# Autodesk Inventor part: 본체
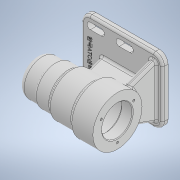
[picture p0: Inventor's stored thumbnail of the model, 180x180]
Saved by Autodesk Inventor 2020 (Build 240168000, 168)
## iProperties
Created: 2021-10
Part Number: 본체
Material: 일반
Document SubType Name: Modeling
Designer: user
Density: 1 g/cm^3
Appearance: 기본값
Author: user
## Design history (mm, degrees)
sketch "스케치1"
  geometry: L1 (-56, -45)-(56, -45); L2 (56, -45)-(56, 45); L3 (56, 45)-(-56, 45); L4 (-56, 45)-(-56, -45); L5 (-56, -45)-(56, 45); L6 (56, -45)-(-56, 45); 1 further point
  constraints: 12 end point, 2 midpoint, 2 parallel, 1 horizontal, 1 perpendicular
  dimensions: "d0" = 112 distance of L2.end L3.end; "d1" = 90 distance of L3.end L1.start
extrude "돌출1" new body sketch "스케치1" distance "d2" = 8; taper "d3" = 0 deg
sketch "스케치2"
  geometry: L1 (62.238, 70)-(-57.921, 70); L2 (10, 100)-(10, 97); L3 (10, 97)-(32, 97); L4 (32, 97)-(32, 95); L5 (56, 95)-(56, 70); L6 (50, 70)-(50, 77.5); L7 (47, 80.5)-(47, 80.5); L8 (47, 80.5)-(47, 85.7); L9 (46.7, 86)-(43, 86); L10 (43, 86)-(43, 87.2); L11 (25, 87.5)-(25, 90.7); L12 (24.7, 91)-(13, 91); L13 (13, 91)-(13, 91); L14 (10, 94)-(-38, 94); L15 (-41, 91)-(-41, 91); L16 (-41, 91)-(-56, 91); L17 (-56, 0)-(-56, 8) reference; L18 (10, 100)-(-24, 100); L19 (-24, 100)-(-24, 104); L20 (-24, 104)-(-56, 104); L21 (-56, 104)-(-56, 91); L22 (42.7, 87.5)-(25, 87.5); L23 (56, 95)-(32, 95); A1 r 0.3 centre (46.7, 85.7) between (47, 85.7) and (46.7, 86); A2 r 0.3 centre (42.7, 87.2) between (43, 87.2) and (42.7, 87.5); A3 r 0.3 centre (24.7, 90.7) between (25, 90.7) and (24.7, 91); A4 r 3 centre (47, 77.5) between (50, 77.5) and (47, 80.5); A5 r 3 centre (10, 91) between (13, 91) and (10, 94); A6 r 3 centre (-38, 91) between (-38, 94) and (-41, 91); 5 further points
  constraints: 44 end point, 13 perpendicular, 12 point on circle, 12 tangent, 6 centre point, 4 equal radius, 4 point on line, 3 horizontal, 1 vertical
  dimensions: "d4" = 70 distance from line of point (0, 0) L1; "d5" = 120.15879 distance of L1.start L1.end; "d8" = 24 distance between parallel lines of L4 L5; "d9" = 46 distance between parallel lines of L2 L5; "d10" = 112 distance between parallel lines of L21 L5; "d11" = 80 distance between parallel lines of L19 L5; "d12" = 15 distance between parallel lines of L15 L21; "d14" = 6 distance between parallel lines of L6 L5; "d15" = 3 distance between parallel lines of L8 L6; "d16" = 4 distance from line of L9.end L8; "d17" = 18 distance from line of L11 L9.end; "d18" = 12 distance from line of point (13, 94) L11; "d19" = 42 diameter of L16 L1; "d20" = 48 diameter of L14 L1; "d21" = 21 diameter of L7 L1; "d22" = 32 diameter of L9 L1; "d23" = 35 diameter of L22 L1; "d24" = 42 diameter of L12 L1; "d25" = 50 diameter of L23 L1; "d26" = 54 diameter of L3 L1; "d27" = 60 diameter of L18 L1; "d28" = 68 diameter of L20 L1; "d29" = 56 distance from line of point (0, 0) L5; "d30" = 0.3 radius of A1; "d31" = 3 radius of A4
revolve "회전1" sketch "스케치2" stored, may be unused: angle "d32" = 90 deg
sketch "스케치4"
  geometry: L1 (-29, 4)-(48, 4); L2 (48, 4)-(48, -4); L3 (48, -4)-(-29, -4); L4 (-29, -4)-(-29, 4); L5 (-29, 4)-(48, -4); L6 (48, 4)-(-29, -4); L7 (56, -45)-(56, 45) reference; 2 further points
  constraints: 12 end point, 2 midpoint, 2 parallel, 1 horizontal, 1 perpendicular
  dimensions: "d34" = 8 distance between parallel lines of L7 L2; "d35" = 77 distance of L2.end L3.end; "d36" = 8 distance of L1.end L2.end; "d37" = 0 vertical distance of point (0, 0) point (9.5, 0)
extrude "돌출2" join sketch "스케치4" stored distance "d38" = 8; taper "d39" = 0 deg
sketch "스케치5"
  geometry: L1 (0, 49)-(0, -41) reference; L2 (0, -33)-(-37.342, -19.409); L3 (0, 41)-(-37.342, 27.409); A1 r 34 centre (-62, 4) between (-28.236, 8) and (-28.236, 0) reference; 1 further point
  constraints: 4 end point, 2 point on circle, 2 point on line
  dimensions: "d40" = 8 distance of L1.end L2.start; "d41" = 8 distance of L1.start L3.start; "d42" = 110 deg angle of L1 L2; "d43" = 110 deg angle of L1 L3
feature "리브1" sketch "스케치5" dims "d44" = 1, "d45" = 8, "d46" = 0, "d47" = 0, "d48" = 1, "d49" = 1
sketch "스케치6"
  geometry: L1 (28.236, 41)-(28.236, -49) reference; L2 (28.236, 33)-(-9.106, 19.409); A1 r 34 centre (-33.764, -4) between (0, 0) and (0, -8) reference; 1 further point
  constraints: 2 end point, 1 point on circle, 1 point on line
  dimensions: "d50" = 8 distance of L1.start L2.start; "d51" = 110 deg angle of L1 L2
feature "리브2" sketch "스케치6" dims "d52" = 1, "d53" = 8, "d54" = 0, "d55" = 0, "d56" = 1, "d57" = 1
feature "면 기울기1" dims angle "d59" = 15 deg
sketch "스케치8"
  geometry: L1 (-48, 33)-(-24, 33); L2 (-43.5, 28.5)-(-28.5, 28.5); L3 (-28.5, 37.5)-(-43.5, 37.5); L4 (-56, 45)-(-56, -45) reference; L5 (-8, 33)-(16, 33); L6 (-3.5, 28.5)-(11.5, 28.5); L7 (11.5, 37.5)-(-3.5, 37.5); A1 r 4.5 centre (-43.5, 33) between (-43.5, 37.5) and (-43.5, 28.5); A2 r 4.5 centre (-28.5, 33) between (-28.5, 28.5) and (-28.5, 37.5); A3 r 4.5 centre (-3.5, 33) between (-3.5, 37.5) and (-3.5, 28.5); A4 r 4.5 centre (11.5, 33) between (11.5, 28.5) and (11.5, 37.5); 3 further points
  constraints: 16 end point, 12 point on circle, 8 tangent, 4 centre point, 4 point on line, 2 horizontal, 2 midpoint, 2 parallel
  dimensions: "d60" = 9 diameter of A2; "d61" = 15 distance of A2.centre A1.centre; "d62" = 20 distance from line of L4 point (-36, 33); "d63" = 33 vertical distance of point (0, 0) point (-36, 33); "d64" = 9 diameter of A4; "d65" = 15 distance of A4.centre A3.centre; "d66" = 25 distance of A2.centre A3.centre; "d67" = 33 vertical distance of point (0, 0) point (4, 33)
extrude "돌출3" cut sketch "스케치8" distance "d68" = 20; taper "d69" = 0 deg
sketch "스케치9"
  geometry: L1 (-56, 45)-(-56, -45) reference; A1 r 4.5 centre (-43.5, 33) between (-43.5, 37.5) and (-43.5, 28.5) reference; 2 further points
  constraints: 1 other
  dimensions: "d70" = 12 distance from line of L1 point (-44, 0); "d71" = 33 vertical distance of point (-44, 0) A1.centre
feature "엠보싱1" sketch "스케치9" dims "d0" = 112, "d1" = 90, "d4" = 70, "d5" = 120.15879, "d8" = 24, "d9" = 46, "d10" = 112, "d11" = 80, "d12" = 15, "d14" = 6, "d15" = 3, "d16" = 4, "d17" = 18, "d18" = 12, "d19" = 42, "d20" = 48, "d21" = 21, "d22" = 32, "d23" = 35, "d24" = 42, "d25" = 50, "d26" = 54, "d27" = 60, "d28" = 68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
sketch "스케치10"
  geometry: L1 (0, 0)-(-22.517, 13); L2 (0, 0)-(0, -26); C1 r 34 at (0, 0) reference; C2 r 7.5 at (0, 0) reference; A1 r 26 centre (0, 0) between (0, -26) and (-22.517, 13); 2 further points
  constraints: 4 end point, 2 coincident, 2 point on circle, 1 centre point, 1 vertical
  dimensions: "d74" = 52 diameter of A1; "d75" = 120 deg angle of L2 L1
hole "구멍1" sketch "스케치10" at (-22.517, 13) diameter "d76" = 3.242; stored, may be unused: countersink angle "d80" = 90 deg, drill point angle "d82" = 118 deg; dims "d77" = 8, "d78" = 4, "d79" = 2, "d81" = 11
fillet "모깎기1" dims "d86" = 8
fillet "모깎기2" dims "d87" = 12
fillet "모깎기3" dims "d88" = 3
fillet "모깎기4" dims "d89" = 3
fillet "모깎기5" dims "d90" = 3
fillet "모깎기6" dims "d91" = 3
chamfer "모따기1" distance "d92" = 1; stored, may be unused: second distance "d93" = 2, angle "d94" = 45 deg
fillet "모깎기7" dims "d95" = 3
fillet "모깎기8" dims "d96" = 3
fillet "모깎기9" dims "d97" = 3
node "솔리드1"
mirror "미러1"
pattern_circular "원형 패턴1" dims angle "d84" = 360 deg
feature "A9D066F2-1C7D-4E18-AEED-F7BC21143FA4" dims "d76" = 3.242, "d77" = 8, "d78" = 4, "d79" = 2, "d80" = 90 deg, "d81" = 11, "d82" = 118 deg
